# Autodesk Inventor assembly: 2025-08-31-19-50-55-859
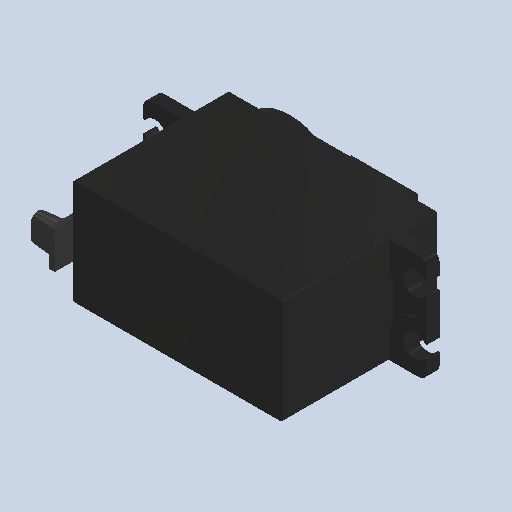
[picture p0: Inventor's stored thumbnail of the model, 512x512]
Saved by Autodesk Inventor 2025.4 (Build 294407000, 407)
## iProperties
Created: 2026-09
Part Number: 2025-08-31-19-50-55-859
Document SubType Name: Assembly
Designer: AdminForWorker
Title: com_top
Author: AdminForWorker
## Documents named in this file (3)
- c:\worker\convert-fusion-r05-cosv3\tmp\job-1\19\temp\files\ca3d996b-dda0-445d-8bee-12a194174ca8\com_top_1.iam
- c:\worker\convert-fusion-r05-cosv3\tmp\job-1\19\temp\files\ca3d996b-dda0-445d-8bee-12a194174ca8\Component8.ipt
- c:\worker\convert-fusion-r05-cosv3\tmp\job-1\19\temp\files\ca3d996b-dda0-445d-8bee-12a194174ca8\Part14.ipt
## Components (2 placed, 2 different names)
1. Component8:1
2. Part14
